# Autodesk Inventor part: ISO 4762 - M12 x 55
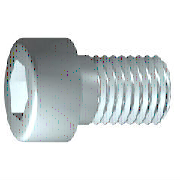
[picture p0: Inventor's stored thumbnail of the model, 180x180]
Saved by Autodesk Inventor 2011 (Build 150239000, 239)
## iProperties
Created: 2010-02
Part Number: ISO 4762 - M12 x 55
Material: Stainless Steel, 440C
Description: Hexagon Socket Head Cap Screw
Document SubType Name: Modeling
Standard: ISO 4762
Designer: 129877
Standard Revision: Fourth edition 2004-03-01
Standards Organization: ISO
Language: en-US
Size Designation: M12 x 55
Categories: <MemberInstance><Categories><Category DisplayName="Fasteners" InternalName="e4da775c-781d-43d5-af7c-5136215cf5a6" Mnemonic="FSTN"><Category DisplayName="Bolts"
Density: 7.75 g/cm^3
Mass: 66.6802 g
Surface Area: 34.358 cm^2
Volume: 8.6039 cm^3
IsCustomPart: 0
Author: 129877
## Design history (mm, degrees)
body "Solid1"
workplane "Work Plane1"
fillet "Fillet2" dims "d30" = 0.1 (= R)
revolve "Body" stored, may be unused: angle "d10" = 90 deg
sketch "Sketch2"
  geometry: L1 (0, -12.6)-(0, 12.6) reference; L2 (-12.6, 0)-(12.6, 0) reference; L3 (5.774, 0)-(2.887, -5); L4 (2.887, -5)-(-2.887, -5); L5 (-2.887, -5)-(-5.774, 0); L6 (-5.774, 0)-(-2.887, 5); L7 (-2.887, 5)-(2.887, 5); L8 (2.887, 5)-(5.774, 0); 2 further points
  constraints: 12 end point, 1 coincident, 1 horizontal alignment, 1 point on line, 12 other
extrude "Slot" join sketch "Sketch2" stored distance "d11" = 10; taper "d12" = 0 deg
fillet "Fillet1" dims "d17" = 1.2 (= RR)
feature "Thread" dims "d13" = 36 (= GEL), "d14" = 0
chamfer "Chamfer1" distance "d15" = 1.07354 (= -0.5 x SPD + 0.5 x GD); stored, may be unused: second distance "d16" = 1.07354 (= GUL), angle "d27" = 45 deg
sketch "Sketch1"
  geometry: L1 (-2.667, 0)-(55, 0); L2 (55, 0)-(55, 6); L3 (55, 6)-(19, 6); L4 (19, 6)-(17.926, 6); L5 (17.926, 6)-(0, 6); L6 (0, 6)-(0, 9); L7 (0, 9)-(-12, 9); L8 (-12, 9)-(-12, 5.774); L9 (-12, 5.774)-(-6, 5.774); L10 (-6, 5.774)-(-2.667, 0); L11 (-25.4, 0)-(68.4, 0) reference; L12 (0, -1.8)-(0, 10.8) reference; L13 (19, 6)-(0, 6)
  constraints: 22 end point, 6 parallel, 2 collinear, 2 perpendicular, 1 horizontal, 1 point on line
  dimensions: "d1" = 36 distance from line of L3.end L2 (= GEL); "d2" = 1.07364 distance of L4.end L3.end (computed from GAL); "d3" = 12 distance between parallel lines of L8 L6 (= KOH); "d4" = 6 distance of L8.end L9.end (= INTI); "d5" = 60 deg angle of L10 L1; "d6" = 12 diameter of L3 L1 (= GD); "d7" = 12 diameter of L5 L1 (= BDM); "d8" = 11.54701 diameter of L9 L1 (= 1.1547 x SW); "d9" = 18 diameter of L7 L1 (= KOD); "d26" = 55 distance between parallel lines of L12 L2 (= NLG)
other parameters: "GD" = 12 [user parameter; used in 2 equation terms], "NLG" = 55 [user parameter; used in 1 equation term], "GEL" = 36 [user parameter; used in 2 equation terms], "KOD" = 18 [user parameter; used in 1 equation term], "KOH" = 12 [user parameter; used in 1 equation term], "INTI" = 6 [user parameter; used in 1 equation term], "GAL" = 1.07354 (= 0.61345 x PTC) [user parameter; used in 1 equation term], "GUL" = 1.07354 (= 0.61345 x PTC) [user parameter; used in 1 equation term], "BDM" = 12 (= NND) [user parameter; used in 1 equation term], "RR" = 1.2 [user parameter; used in 1 equation term], "SPD" = 9.85293 (= NND - 1.2269 x PTC) [user parameter; used in 1 equation term], "d19" = 0, "d28" = 0, "d29" = 0, "R" = 0.1 [user parameter; used in 1 equation term], "TOA" = 30 deg [user parameter], "GD1" = 9.85293 (= THREADDIA - 1.2269 x PTC) [user parameter], "THREADDIA" = 12 [user parameter; used in 1 equation term], "FAWI" = 45 deg [user parameter], "TPU" = 5.71429 (computed from PTC) [user parameter], "PTC" = 1.75 [user parameter; used in 5 equation terms], "NND" = 12 [user parameter; used in 2 equation terms], "E0" = 11.55 (= 1.155 x SW) [user parameter]
